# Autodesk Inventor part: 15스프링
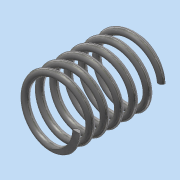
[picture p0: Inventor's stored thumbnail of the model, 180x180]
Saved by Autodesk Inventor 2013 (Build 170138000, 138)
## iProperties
Created: 2019-07
Part Number: 15스프링
Material: 강철, 탄소
Document SubType Name: Modeling
Designer: Administrator
Density: 7.87 g/cm^3
Mass: 7.7901 g
Surface Area: 20.0705 cm^2
Volume: 0.989848 cm^3
Author: Administrator
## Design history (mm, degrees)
sketch "스케치1"
  geometry: L1 (0, 0)-(0, 25.33); L2 (0, 0)-(8.5, 0); L3 (0, 25.33)-(8.5, 25.33); C1 r 1 at (8.5, 0)
  constraints: 6 end point, 2 parallel, 1 centre point, 1 coincident, 1 perpendicular, 1 vertical
  dimensions: "d0" = 25.33013 distance of L1.start L1.end (derived); "d1" = 2 diameter of C1; "d2" = 17 diameter of C1.centre L1
feature "코일1" sketch "스케치1" pitch "d3" = 10; turns "d5" = 6; dims "d4" = 25.33013 (= d0), "d6" = 0, angle "d7" = 90 deg, angle "d8" = 90 deg, "d9" = 0, "d10" = 0
sketch "스케치2"
  geometry: L1 (25.33, 15)-(0, 15); L2 (0, 15)-(0, -15); L3 (0, -15)-(25.33, -15); L4 (25.33, -15)-(25.33, 15); 2 further points
  constraints: 8 end point, 2 parallel, 1 coincident, 1 horizontal, 1 midpoint, 1 perpendicular
  dimensions: "d11" = 30 distance of L3.end L1.start; "d13" = 25.33013 distance of L2.end L3.end (= d0)
extrude "돌출1" sketch "스케치2" stored distance "d14" = 10; taper "d15" = 0 deg
node "솔리드1"
